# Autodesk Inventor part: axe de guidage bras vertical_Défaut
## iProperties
Shininess: 64.0
Length Units: 11269
Angle Units: 11279
Time Units: 11290
Mass Units: 11283
Length Display Precision: 3
Angle Display Precision: 2
Compacted: True
Part Number: axe de guidage bras vertical_Défaut
Document SubType Name: Modeling
Created: 2006-11
Material: Par défaut
Designer: profs_sti
Density: 0.0
Volumn: 0.0
Area: 0.0
PropertySet Name: Model Information
Control State: 0
Master: False
Checked Out: False
Author: profs_sti
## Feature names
1. Base1
